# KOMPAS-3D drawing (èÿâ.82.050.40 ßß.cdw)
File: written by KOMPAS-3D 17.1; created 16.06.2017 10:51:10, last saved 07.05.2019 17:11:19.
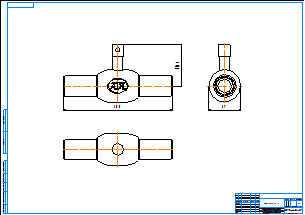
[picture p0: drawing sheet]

Sheet 1: A1, landscape

Title block, sheet 1: name: КШГ.82.050.40 сс; material: Внимание! Данный продукт является объектом авторского права ООО «Торговый Дом АДЛ». / Запрещается изменение, копирование, распространение / (в том числе путем копирования на другие сайты и ресурсы в Интернете) / или любое иное использование информации и объектов без предварительного / согласия правообладателя (ООО «Торговый Дом АДЛ»).; scale: 1:1; sheets: 1; organisation: ООО "Торговый дом АДЛ"; sheet format: A1; stored path: C:\Users\tra\Desktop\2д чертежи\Шаровые краны БИВАЛ\КШ_Бивал_серия_82_85\KOMPAS 2D\КШГ.82.050.40 сс.cdw

Views: Спереди 1, Проекционный вид 2, Проекционный вид 3
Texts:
  Klimkovich
  ADL
Dimensions and other numbers on the sheet: 300; 115,9; 89; 1:1; 1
